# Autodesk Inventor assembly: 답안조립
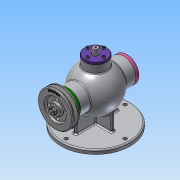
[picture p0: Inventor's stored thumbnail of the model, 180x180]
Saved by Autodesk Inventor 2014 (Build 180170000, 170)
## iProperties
Created: 2020-08
Part Number: 답안조립
Document SubType Name: Assembly
Designer: net
Author: net
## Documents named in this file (18)
- C:\Users\net\Desktop\700806V1016\답안조립.iam
- C:\Users\net\Desktop\700806V1016\본체.ipt
- C:\Users\net\Desktop\700806V1016\뒤커버.ipt
- C:\Users\net\Desktop\700806V1016\볼트 M4.ipt
- C:\Users\net\Desktop\700806V1016\상부커버.ipt
- C:\Users\net\Desktop\700806V1016\앞커버.ipt
- C:\Users\net\Desktop\700806V1016\베어링 6202.ipt
- 베어링 6202.ipt
- C:\Users\net\Desktop\700806V1016\편심축.ipt
- C:\Users\net\Desktop\700806V1016\칼라.ipt
- C:\Users\net\Desktop\700806V1016\키 3x3x12.ipt
- C:\Users\net\Desktop\700806V1016\V-벨트풀리.ipt
- C:\Users\net\Desktop\700806V1016\너트 M8.ipt
- C:\Users\net\Desktop\700806V1016\오일 실 15 30 7.ipt
- C:\Users\net\Desktop\700806V1016\슬라이드.ipt
- C:\Users\net\Desktop\700806V1016\멈춤링 15x1.ipt
- C:\Users\net\Desktop\700806V1016\멈춤링 35x1.6.ipt
- 멈춤링 35x1.6.ipt
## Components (1 placed, 1 different names)
1. V-벨트풀리:1
